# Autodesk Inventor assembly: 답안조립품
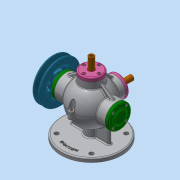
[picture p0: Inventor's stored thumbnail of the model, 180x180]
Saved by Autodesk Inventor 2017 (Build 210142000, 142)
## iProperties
Part Number: 답안조립품
Material: 일반
Document SubType Name: Assembly
Designer: MRC
Mass: 3721.38 g
Surface Area: 2584.17 cm^2
Volume: 938.795 cm^3
Density: 3.96399 g/cm^3
Author: MRC
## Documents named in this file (17)
- C:\Users\MRC\Desktop\620909V1001\620909V1001\답안조립품.iam
- C:\Users\MRC\Desktop\620909V1001\620909V1001\본체.ipt
- C:\Users\MRC\Desktop\620909V1001\620909V1001\V-벨트풀리.ipt
- C:\Users\MRC\Desktop\620909V1001\620909V1001\너트-M8x1.ipt
- C:\Users\MRC\Desktop\620909V1001\620909V1001\뒤커버.ipt
- C:\Users\MRC\Desktop\620909V1001\620909V1001\베어링- 6202.ipt
- C:\Users\MRC\Desktop\620909V1001\620909V1001\본체커버.ipt
- C:\Users\MRC\Desktop\620909V1001\620909V1001\볼트 M4x0.7.ipt
- C:\Users\MRC\Desktop\620909V1001\620909V1001\슬라이드 커버.ipt
- C:\Users\MRC\Desktop\620909V1001\620909V1001\슬라이드.ipt
- C:\Users\MRC\Desktop\620909V1001\620909V1001\앞커버.ipt
- C:\Users\MRC\Desktop\620909V1001\620909V1001\오일실.ipt
- C:\Users\MRC\Desktop\620909V1001\620909V1001\와셔 8x17.ipt
- C:\Users\MRC\Desktop\620909V1001\620909V1001\축.ipt
- C:\Users\MRC\Desktop\620909V1001\620909V1001\키-4x4.ipt
- C:\Users\MRC\Desktop\620909V1001\620909V1001\스프링.ipt
- C:\Users\MRC\Desktop\620909V1001\620909V1001\스프링2.ipt
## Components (18 placed, 2 different names)
1. V-벨트풀리:1
2. M4x0.7x12:17
3. M4x0.7x12:1
4. M4x0.7x12:3
5. M4x0.7x12:4
6. M4x0.7x12:5
7. M4x0.7x12:2
8. M4x0.7x12:6
9. M4x0.7x12:7
10. M4x0.7x12:8
11. M4x0.7x12:10
12. M4x0.7x12:11
13. M4x0.7x12:12
14. M4x0.7x12:13
15. M4x0.7x12:9
16. M4x0.7x12:14
17. M4x0.7x12:15
18. M4x0.7x12:16
